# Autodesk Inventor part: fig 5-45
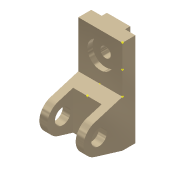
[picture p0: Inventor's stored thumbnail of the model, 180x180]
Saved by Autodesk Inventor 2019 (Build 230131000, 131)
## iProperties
Shininess: 65.0
Angle Display Precision: 2
Document Length Units: 11269
Document Angle Units: 11279
Document Time Units: 11290
Document Mass Units: 11283
Document Length Units Precision: 3
Document Angle Units Precision: 2
Created: 2001-11
Part Number: fig 5-45
Document SubType Name: Modeling
Designer: Renu Muthoo
Density: 1 g/cm^3
Material: Generic
Appearance: Metal-Titanium (Polished)
Density: 0.0
Volumn: 0.0
Area: 0.0
PropertySet Name: Model Information
Control State: 0
Master: False
Checked Out: False
Author: Renu Muthoo
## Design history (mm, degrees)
node "Sketch1"
sketch "Sketch2"
  geometry: L1 (33.257, 104.664)-(33.257, -75.336); L2 (33.257, -75.336)-(8.257, -75.336); L3 (8.257, -75.336)-(-45.451, -59.045); L4 (-45.451, -1.628)-(8.257, 14.664); L5 (8.257, 14.664)-(8.257, 104.664); L6 (8.257, 104.664)-(33.257, 104.664); C1 r 15 at (-36.743, -30.336); A1 r 30 centre (-36.743, -30.336) between (-45.451, -1.628) and (-45.451, -59.045)
  constraints: 12 end point, 2 centre point, 2 equal length, 2 parallel, 2 point on circle, 2 tangent, 1 coincident, 1 perpendicular, 1 vertical
  dimensions: "d0" = 180 distance of L1.start L1.end; "d1" = 30 radius of A1; "d2" = 25 distance of L5.end L1.start; "d3" = 45 distance from line of L2 A1.centre; "d4" = 70 distance from line of L1 A1.centre; "d5" = 30 diameter of C1
extrude "Extrusion1" new body sketch "Sketch2" distance "d6" = 85; taper "d7" = 0 deg
workplane "Work Plane1"
sketch "Sketch3"
  geometry: L1 (15, 62.364)-(70, 62.364); L2 (70, 62.364)-(70, -52.386); L3 (70, -52.386)-(15, -52.386); L4 (15, -52.386)-(15, 62.364); L5 (0, -45)-(0, -28.708) reference
  constraints: 8 end point, 2 parallel, 1 horizontal, 1 perpendicular
  dimensions: "d8" = 55 distance of L1.start L1.end; "d9" = 15 distance between parallel lines of L5 L4
extrude "Extrusion2" cut sketch "Sketch3" distance "d10" = 50; taper "d11" = 0 deg
sketch "Sketch4"
  geometry: L1 (0, 25)-(85, 25) reference; L2 (0, 0)-(0, 25) reference; L3 (20, 25)-(65, 25); L4 (65, 25)-(65, 35); L5 (65, 35)-(20, 35); L6 (20, 35)-(20, 25)
  constraints: 8 end point, 2 parallel, 1 horizontal, 1 perpendicular, 1 point on line
  dimensions: "d12" = 45 distance of L4.end L5.end; "d13" = 10 distance of L3.end L4.end; "d14" = 20 distance between parallel lines of L2 L6
extrude "Extrusion3" join sketch "Sketch4" stored distance "d15" = 50; taper "d16" = 0 deg
sketch "Sketch5"
  geometry: L1 (85, 0)-(85, 90) reference; L2 (0, 90)-(85, 90) reference; 1 further point
  dimensions: "d17" = 42 distance from line of L2 point (42.5, 48); "d18" = 42.5 distance from line of L1 point (42.5, 48)
hole "Hole1" sketch "Sketch5" at (42.5, 48) diameter "d19" = 20; stored, may be unused: countersink angle "d23" = 82 deg, drill point angle "d25" = 118 deg; dims "d20" = 6, "d21" = 50, "d22" = 10, "d24" = 8
workpoint "Work Point1"
workpoint "Work Point2"
workpoint "Work Point3"
workpoint "Work Point4"
workpoint "Work Point5"
body "Solid1"
